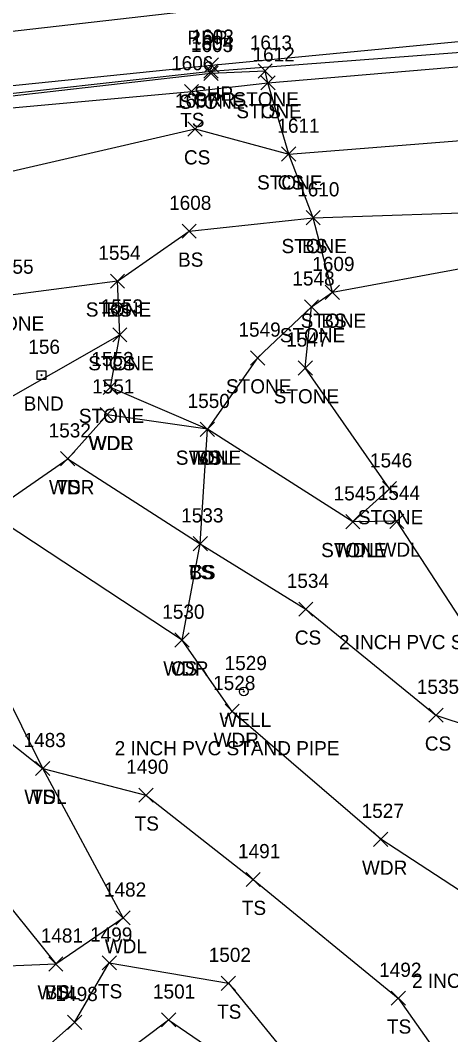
# Model space of a CAD drawing. Extents: x 49137 to 50946, y 9590 to 10709.
# Drawn here: x 50177.5 to 50238.1, y 9912 to 10054.9 of the extents above; entities that cross this region are included whole.
import ezdxf

# ---------------------------------------------------------------- set-up
doc = ezdxf.new("R2010")
doc.units = 0
for name, color, linetype in [('L_A', 7, 'Continuous'), ('L_I', 7, 'Continuous'), ('L_TIC', 7, 'Continuous'), ('LASF', 7, 'Continuous'), ('LAWA', 7, 'Continuous'), ('LAWE', 7, 'Continuous'), ('LELB', 7, 'Continuous'), ('M_A', 7, 'Continuous'), ('M_I', 7, 'Continuous'), ('MHBP', 7, 'Continuous'), ('P_A', 7, 'Continuous'), ('P_I', 7, 'Continuous'), ('P_TIC', 7, 'Continuous'), ('PET', 7, 'Continuous'), ('PSP', 7, 'Continuous'), ('R_A', 7, 'Continuous'), ('R_I', 7, 'Continuous'), ('R_TIC', 7, 'Continuous'), ('RGR', 7, 'Continuous'), ('U_A', 7, 'Continuous'), ('U_C', 7, 'Continuous'), ('U_I', 7, 'Continuous'), ('UWW', 7, 'Continuous')]:
    doc.layers.add(name, color=color, linetype=linetype)

msp = doc.modelspace()

# ---------------------------------------------------------------- linework, layer by layer
at = {"layer": 'L_TIC'}
for points in [[(50203.29, 10046.45), (50205.29, 10048.45)], [(50205.29, 10046.45), (50203.29, 10048.45)], [(50210.93, 10046.79), (50212.93, 10048.79)], [(50212.93, 10046.79), (50210.93, 10048.79)], [(50210.93, 10046.79), (50212.93, 10048.79)], [(50212.93, 10046.79), (50210.93, 10048.79)], [(50211.32, 10045.12), (50213.32, 10047.12)], [(50213.32, 10045.12), (50211.32, 10047.12)], [(50211.32, 10045.12), (50213.32, 10047.12)], [(50213.32, 10045.12), (50211.32, 10047.12)], [(50200.55, 10043.88), (50202.55, 10045.88)], [(50202.55, 10043.88), (50200.55, 10045.88)], [(50201.05, 10038.61), (50203.05, 10040.61)], [(50203.05, 10038.61), (50201.05, 10040.61)], [(50214.24, 10035.08), (50216.24, 10037.08)], [(50216.24, 10035.08), (50214.24, 10037.08)], [(50214.24, 10035.08), (50216.24, 10037.08)], [(50216.24, 10035.08), (50214.24, 10037.08)], [(50217.69, 10026.11), (50219.69, 10028.11)], [(50219.69, 10026.11), (50217.69, 10028.11)], [(50217.69, 10026.11), (50219.69, 10028.11)], [(50219.69, 10026.11), (50217.69, 10028.11)], [(50217.69, 10026.11), (50219.69, 10028.11)], [(50219.69, 10026.11), (50217.69, 10028.11)], [(50200.22, 10024.2), (50202.22, 10026.2)], [(50202.22, 10024.2), (50200.22, 10026.2)], [(50190.13, 10017.17), (50192.13, 10019.17)], [(50192.13, 10017.17), (50190.13, 10019.17)], [(50190.13, 10017.17), (50192.13, 10019.17)], [(50192.13, 10017.17), (50190.13, 10019.17)], [(50220.39, 10015.59), (50222.39, 10017.59)], [(50222.39, 10015.59), (50220.39, 10017.59)], [(50220.39, 10015.59), (50222.39, 10017.59)], [(50222.39, 10015.59), (50220.39, 10017.59)], [(50217.45, 10013.55), (50219.45, 10015.55)], [(50219.45, 10013.55), (50217.45, 10015.55)], [(50217.45, 10013.55), (50219.45, 10015.55)], [(50219.45, 10013.55), (50217.45, 10015.55)], [(50190.47, 10009.6), (50192.47, 10011.6)], [(50192.47, 10009.6), (50190.47, 10011.6)], [(50190.47, 10009.6), (50192.47, 10011.6)], [(50192.47, 10009.6), (50190.47, 10011.6)], [(50209.87, 10006.34), (50211.87, 10008.34)], [(50211.87, 10006.34), (50209.87, 10008.34)], [(50216.58, 10004.94), (50218.58, 10006.94)], [(50218.58, 10004.94), (50216.58, 10006.94)], [(50189.14, 10002.19), (50191.14, 10004.19)], [(50191.14, 10002.19), (50189.14, 10004.19)], [(50188.69, 9998.35), (50190.69, 10000.35)], [(50190.69, 9998.35), (50188.69, 10000.35)], [(50188.69, 9998.35), (50190.69, 10000.35)], [(50190.69, 9998.35), (50188.69, 10000.35)], [(50202.79, 9996.29), (50204.79, 9998.29)], [(50204.79, 9996.29), (50202.79, 9998.29)], [(50202.79, 9996.29), (50204.79, 9998.29)], [(50204.79, 9996.29), (50202.79, 9998.29)], [(50202.79, 9996.29), (50204.79, 9998.29)], [(50204.79, 9996.29), (50202.79, 9998.29)], [(50183.13, 9992.14), (50185.13, 9994.14)], [(50185.13, 9992.14), (50183.13, 9994.14)], [(50183.13, 9992.14), (50185.13, 9994.14)], [(50185.13, 9992.14), (50183.13, 9994.14)], [(50228.44, 9987.91), (50230.44, 9989.91)], [(50230.44, 9987.91), (50228.44, 9989.91)], [(50223.27, 9983.27), (50225.27, 9985.27)], [(50225.27, 9983.27), (50223.27, 9985.27)], [(50223.27, 9983.27), (50225.27, 9985.27)], [(50225.27, 9983.27), (50223.27, 9985.27)], [(50229.47, 9983.33), (50231.47, 9985.33)], [(50231.47, 9983.33), (50229.47, 9985.33)], [(50201.79, 9980.16), (50203.79, 9982.16)], [(50203.79, 9980.16), (50201.79, 9982.16)], [(50201.79, 9980.16), (50203.79, 9982.16)], [(50203.79, 9980.16), (50201.79, 9982.16)], [(50201.79, 9980.16), (50203.79, 9982.16)], [(50203.79, 9980.16), (50201.79, 9982.16)], [(50216.66, 9970.94), (50218.66, 9972.94)], [(50218.66, 9970.94), (50216.66, 9972.94)], [(50199.22, 9966.59), (50201.22, 9968.59)], [(50201.22, 9966.59), (50199.22, 9968.59)], [(50199.22, 9966.59), (50201.22, 9968.59)], [(50201.22, 9966.59), (50199.22, 9968.59)], [(50206.29, 9956.54), (50208.29, 9958.54)], [(50208.29, 9956.54), (50206.29, 9958.54)], [(50234.97, 9956.01), (50236.97, 9958.01)], [(50236.97, 9956.01), (50234.97, 9958.01)], [(50179.6, 9948.5), (50181.6, 9950.5)], [(50181.6, 9948.5), (50179.6, 9950.5)], [(50179.6, 9948.5), (50181.6, 9950.5)], [(50181.6, 9948.5), (50179.6, 9950.5)], [(50194.14, 9944.74), (50196.14, 9946.74)], [(50196.14, 9944.74), (50194.14, 9946.74)], [(50227.2, 9938.52), (50229.2, 9940.52)], [(50229.2, 9938.52), (50227.2, 9940.52)], [(50209.23, 9932.85), (50211.23, 9934.85)], [(50211.23, 9932.85), (50209.23, 9934.85)], [(50190.92, 9927.44), (50192.92, 9929.44)], [(50192.92, 9927.44), (50190.92, 9929.44)], [(50181.45, 9920.95), (50183.45, 9922.95)], [(50183.45, 9920.95), (50181.45, 9922.95)], [(50181.45, 9920.95), (50183.45, 9922.95)], [(50183.45, 9920.95), (50181.45, 9922.95)], [(50188.98, 9921.1), (50190.98, 9923.1)], [(50190.98, 9921.1), (50188.98, 9923.1)], [(50205.75, 9918.23), (50207.75, 9920.23)], [(50207.75, 9918.23), (50205.75, 9920.23)], [(50229.67, 9916.13), (50231.67, 9918.13)], [(50231.67, 9916.13), (50229.67, 9918.13)], [(50197.34, 9913.07), (50199.34, 9915.07)], [(50199.34, 9913.07), (50197.34, 9915.07)], [(50184.1, 9912.72), (50186.1, 9914.72)], [(50186.1, 9912.72), (50184.1, 9914.72)]]:
    msp.add_lwpolyline(points, dxfattribs=at)
at = {"layer": 'LASF'}
for points in [[(50075.14, 9979.09), (50069.31, 9989.49), (50063.31, 10003.63), (50083.24, 10011.13), (50103.65, 10019.31), (50102.01, 10030.98), (50101.92, 10032.21), (50138.71, 10039.2), (50167.18, 10043.25), (50204.29, 10047.45), (50211.93, 10047.79)], [(50224.27, 9984.27), (50229.44, 9988.91), (50217.58, 10005.94), (50218.45, 10014.55), (50221.39, 10016.59), (50218.69, 10027.11), (50215.24, 10036.08), (50212.32, 10046.12), (50211.93, 10047.79)], [(50218.45, 10014.55), (50210.87, 10007.34), (50203.79, 9997.29), (50190.14, 10003.19), (50191.47, 10010.6), (50191.13, 10018.17), (50176.06, 10016.21), (50169.79, 10016.59), (50164.12, 10007.94)]]:
    msp.add_lwpolyline(points, dxfattribs=at)
at = {"layer": 'LAWA'}
for points in [[(50265.38, 9914.66), (50247, 9927.27), (50228.2, 9939.52), (50207.29, 9957.54), (50200.22, 9967.59), (50173.05, 9985.49), (50184.13, 9993.14), (50189.69, 9999.35)], [(50319.22, 9934.09), (50297.9, 9949.71), (50276.2, 9961.58), (50260.59, 9967.74), (50240.67, 9968.69), (50230.47, 9984.33), (50224.27, 9984.27), (50203.79, 9997.29), (50189.69, 9999.35)], [(50117.09, 9812.03), (50125.19, 9838.2), (50131.44, 9869.96), (50136.76, 9887.6), (50137.75, 9904.59), (50153.56, 9910.03), (50161.77, 9913.05), (50163.42, 9912.91), (50169.87, 9921.06), (50171.08, 9921.49), (50182.45, 9921.95), (50191.92, 9928.44), (50180.6, 9949.5), (50171.66, 9967.48), (50163.03, 9983.02), (50150.28, 9995.84), (50140.4, 9991.18), (50131.52, 9978.47)]]:
    msp.add_lwpolyline(points, dxfattribs=at)
at = {"layer": 'LAWE'}
msp.add_lwpolyline([(50128.8, 9830.05), (50134.29, 9847.3), (50142.11, 9880.9), (50145.47, 9899.84), (50152.79, 9899.24), (50158.84, 9904.9), (50168.73, 9907.32), (50170.14, 9900.19), (50173.37, 9900.16), (50184.59, 9903.76), (50198.34, 9914.07), (50214.56, 9902.92), (50226.92, 9887.06)], dxfattribs=at)
at = {"layer": 'LELB'}
for points in [[(50167.44, 10041.81), (50201.55, 10044.88), (50212.32, 10046.12), (50246.1, 10048.99), (50272.8, 10048.46), (50313.94, 10048.62), (50350.81, 10048.34), (50387.74, 10046.03), (50413.04, 10045.35), (50435.45, 10042.61), (50477, 10035.72), (50497.96, 10034.79)], [(50107.47, 10020.38), (50144.2, 10028.78), (50165.65, 10031.22), (50202.05, 10039.61), (50215.24, 10036.08), (50246.55, 10038.53), (50272.19, 10036.43), (50315.22, 10038.43), (50350.77, 10037.74), (50388.31, 10038.81), (50412.12, 10038.05), (50434.22, 10033.95), (50476.27, 10030.6), (50502.33, 10026.06), (50519.95, 10026.12), (50528.33, 10023.44), (50558.5, 10017.09), (50596.1, 10007.75), (50623.13, 10001.96)], [(50218.69, 10027.11), (50246.54, 10028.02), (50268.1, 10028.33), (50270.89, 10027.37)], [(50191.13, 10018.17), (50201.22, 10025.2), (50218.69, 10027.11)], [(50221.39, 10016.59), (50240.69, 10020.2), (50266.27, 10022.79), (50262.95, 10002.37)], [(50150.28, 9995.84), (50172.85, 9999.99), (50191.47, 10010.6)], [(50202.79, 9981.16), (50203.79, 9997.29)], [(50184.13, 9993.14), (50202.79, 9981.16)], [(50200.22, 9967.59), (50202.79, 9981.16), (50217.66, 9971.94), (50235.97, 9957.01), (50255.74, 9950.49), (50271.41, 9942.16)], [(50154.36, 9970.3), (50163.69, 9962.94), (50180.6, 9949.5), (50195.14, 9945.74), (50210.23, 9933.85), (50230.67, 9917.13), (50242.1, 9900.88)], [(50151.54, 9966.17), (50159.46, 9958.1), (50157.64, 9954.79), (50157.4, 9946.13), (50160.15, 9939.02), (50167.35, 9930.31), (50171.08, 9921.49), (50172.89, 9902.89), (50185.1, 9913.72), (50189.98, 9922.1), (50206.75, 9919.23), (50216.84, 9906.82), (50233.45, 9889.39)], [(50157.64, 9954.79), (50163.27, 9946.54), (50167.1, 9940.71), (50172.95, 9933.72), (50182.45, 9921.95)]]:
    msp.add_lwpolyline(points, dxfattribs=at)
at = {"layer": 'MHBP'}
msp.add_lwpolyline([(50179.81, 10005.55), (50181.06, 10005.55), (50181.06, 10004.3), (50179.81, 10004.3)], close=True, dxfattribs=at)
msp.add_circle((50180.43, 10004.92), 0.0833, dxfattribs=at)
at = {"layer": 'P_TIC'}
for points in [[(50203.38, 10047.62), (50205.38, 10049.62)], [(50205.38, 10047.62), (50203.38, 10049.62)]]:
    msp.add_lwpolyline(points, dxfattribs=at)
at = {"layer": 'PET'}
msp.add_lwpolyline([(49743.42, 9944.81), (49788.35, 9958.02), (49837.04, 9971.51), (49882.75, 9984.49), (49918.64, 9994.5), (49951.14, 10003.99), (49990.91, 10015.05), (50038.8, 10027.76), (50078.38, 10036.75), (50102.79, 10041.88), (50136.94, 10048.02), (50166.81, 10052.31), (50203.48, 10056.47), (50244.74, 10059.59), (50274.3, 10060.67), (50312.69, 10061.26), (50351.88, 10059.79), (50388.42, 10057.55), (50415.03, 10055.45), (50437.05, 10053.05), (50478.42, 10048.42), (50499.95, 10044.65)], dxfattribs=at)
at = {"layer": 'PSP'}
msp.add_lwpolyline([(49745.77, 9936.94), (49791.02, 9949.79), (49838.6, 9962.98), (49884.65, 9976.31), (49920.32, 9986.67), (49952.97, 9996.21), (49993.49, 10007.72), (50041.55, 10020.44), (50079.02, 10029.05), (50103.84, 10034.11), (50138.34, 10040.53), (50167.13, 10044.8), (50204.38, 10048.62), (50245.47, 10052.53), (50273.99, 10052.71), (50313.27, 10053.81), (50350.86, 10052.67), (50388.17, 10050.83), (50414.17, 10048.89), (50435.24, 10046.38), (50477.89, 10041.39), (50498.49, 10037.53)], dxfattribs=at)
at = {"layer": 'R_TIC'}
for points in [[(50203.31, 10046.75), (50205.31, 10048.75)], [(50205.31, 10046.75), (50203.31, 10048.75)]]:
    msp.add_lwpolyline(points, dxfattribs=at)
at = {"layer": 'RGR'}
msp.add_lwpolyline([(49745.96, 9935.74), (49791.34, 9948.66), (49838.49, 9962.28), (49885.39, 9975.73), (49920.7, 9985.37), (49953.18, 9995.29), (49993.74, 10006.79), (50040.75, 10019.43), (50079.3, 10027.88), (50102.09, 10032.68), (50138.52, 10039.64), (50167.15, 10043.61), (50204.31, 10047.75), (50245.69, 10050.91), (50273.98, 10052), (50313.38, 10052.67), (50351, 10051.76), (50388.09, 10049.85), (50414.02, 10047.85), (50436.27, 10045.35), (50477.66, 10040.11), (50498.48, 10036.57)], dxfattribs=at)
at = {"layer": 'UWW'}
for radius in [0.625, 0.0833]:
    msp.add_circle((50208.92, 9960.35), radius, dxfattribs=at)

# ---------------------------------------------------------------- texts
at = {"layer": 'L_A'}
for s, p in [('STONE', (50199.83, 10042.45)), ('STONE', (50207.47, 10042.79)), ('STONE', (50207.47, 10042.79)), ('STONE', (50207.87, 10041.12)), ('TS', (50210.73, 10041.12)), ('TS', (50199.96, 10039.88)), ('CS', (50200.49, 10034.61)), ('STONE', (50210.79, 10031.08)), ('CS', (50213.68, 10031.08)), ('STONE', (50214.23, 10022.11)), ('BS', (50217.13, 10022.11)), ('BS', (50217.13, 10022.11)), ('BS', (50199.66, 10020.2)), ('STONE', (50186.67, 10013.17)), ('BS', (50189.57, 10013.17)), ('STONE', (50216.93, 10011.59)), ('BS', (50219.83, 10011.59)), ('STONE', (50171.61, 10011.21)), ('STONE', (50213.99, 10009.55)), ('STONE', (50213.99, 10009.55)), ('STONE', (50187.02, 10005.6)), ('CS', (50189.91, 10005.6)), ('STONE', (50206.41, 10002.34)), ('STONE', (50213.13, 10000.94)), ('STONE', (50185.69, 9998.19)), ('WDR', (50187.05, 9994.35)), ('WDL', (50187.11, 9994.35)), ('STONE', (50199.34, 9992.29)), ('WDL', (50201.21, 9992.29)), ('BS', (50202.23, 9992.29)), ('WDR', (50181.49, 9988.14)), ('TS', (50182.54, 9988.14)), ('STONE', (50224.98, 9983.91)), ('STONE', (50219.81, 9979.27)), ('WDL', (50221.68, 9979.27)), ('WDL', (50227.89, 9979.33)), ('TS', (50201.2, 9976.16)), ('CS', (50201.23, 9976.16)), ('BS', (50201.23, 9976.16)), ('CS', (50216.1, 9966.94)), ('WDR', (50197.58, 9962.59)), ('CS', (50198.66, 9962.59)), ('WDR', (50204.66, 9952.54)), ('CS', (50234.41, 9952.01)), ('WDL', (50178.02, 9944.5)), ('TS', (50179.01, 9944.5)), ('TS', (50193.55, 9940.74)), ('WDR', (50225.56, 9934.52)), ('TS', (50208.64, 9928.85)), ('WDL', (50189.34, 9923.44)), ('TS', (50188.39, 9917.1)), ('WDL', (50179.87, 9916.95)), ('BS', (50180.89, 9916.95)), ('TS', (50205.16, 9914.23)), ('TS', (50229.08, 9912.13))]:
    msp.add_text(s, height=2, dxfattribs=at).set_placement(p)
at = {"layer": 'L_I'}
for s, p in [('1605', (50201.47, 10050.45)), ('1613', (50209.76, 10050.79)), ('1613', (50209.76, 10050.79)), ('1612', (50210.15, 10049.12)), ('1612', (50210.15, 10049.12)), ('1606', (50198.68, 10047.88)), ('1607', (50199.23, 10042.61)), ('1611', (50213.64, 10039.08)), ('1611', (50213.64, 10039.08)), ('1610', (50216.43, 10030.11)), ('1610', (50216.43, 10030.11)), ('1610', (50216.43, 10030.11)), ('1608', (50198.4, 10028.2)), ('1554', (50188.44, 10021.17)), ('1554', (50188.44, 10021.17)), ('1555', (50173.37, 10019.21)), ('1609', (50218.56, 10019.59)), ('1609', (50218.56, 10019.59)), ('1548', (50215.76, 10017.55)), ('1548', (50215.76, 10017.55)), ('1553', (50188.78, 10013.6)), ('1553', (50188.78, 10013.6)), ('1549', (50208.17, 10010.34)), ('1547', (50214.89, 10008.94)), ('1552', (50187.45, 10006.19)), ('1551', (50187.56, 10002.35)), ('1551', (50187.56, 10002.35)), ('1550', (50201.01, 10000.29)), ('1550', (50201.01, 10000.29)), ('1550', (50201.01, 10000.29)), ('1532', (50181.44, 9996.14)), ('1532', (50181.44, 9996.14)), ('1546', (50226.69, 9991.91)), ('1545', (50221.57, 9987.27)), ('1545', (50221.57, 9987.27)), ('1544', (50227.78, 9987.33)), ('1533', (50200.1, 9984.16)), ('1533', (50200.1, 9984.16)), ('1533', (50200.1, 9984.16)), ('1534', (50214.97, 9974.94)), ('1530', (50197.44, 9970.59)), ('1530', (50197.44, 9970.59)), ('1528', (50204.6, 9960.54)), ('1535', (50233.28, 9960.01)), ('1483', (50177.91, 9952.5)), ('1483', (50177.91, 9952.5)), ('1490', (50192.36, 9948.74)), ('1527', (50225.51, 9942.52)), ('1491', (50208.11, 9936.85)), ('1482', (50189.23, 9931.44)), ('1481', (50180.33, 9924.95)), ('1481', (50180.33, 9924.95)), ('1499', (50187.28, 9925.1)), ('1502', (50203.98, 9922.23)), ('1492', (50227.98, 9920.13)), ('1501', (50196.13, 9917.07)), ('1498', (50182.41, 9916.72))]:
    msp.add_text(s, height=2, dxfattribs=at).set_placement(p)
at = {"layer": 'M_A'}
msp.add_text('BND', height=2, dxfattribs=at).set_placement((50177.92, 9999.92))
at = {"layer": 'M_I'}
msp.add_text('156', height=2, dxfattribs=at).set_placement((50178.58, 10007.92))
at = {"layer": 'P_A'}
for s, p in [('RDP', (50200.97, 10051.47)), ('SHP', (50201.91, 10043.62))]:
    msp.add_text(s, height=2, dxfattribs=at).set_placement(p)
at = {"layer": 'P_I'}
msp.add_text('1603', height=2, dxfattribs=at).set_placement((50201.56, 10051.62))
at = {"layer": 'R_A'}
msp.add_text('GRR', height=2, dxfattribs=at).set_placement((50201.8, 10042.75))
at = {"layer": 'R_I'}
msp.add_text('1604', height=2, dxfattribs=at).set_placement((50201.49, 10050.75))
at = {"layer": 'U_A'}
msp.add_text('WELL', height=2, dxfattribs=at).set_placement((50205.49, 9955.35))
at = {"layer": 'U_C'}
for s, p in [('2 INCH PVC STAND PIPE INCASAE 4', (50222.31, 9966.3)), ('2 INCH PVC STAND PIPE', (50190.74, 9951.35)), ('2 INCH PVC STAND PIPE', (50232.62, 9918.58))]:
    msp.add_text(s, height=2, dxfattribs=at).set_placement(p)
at = {"layer": 'U_I'}
msp.add_text('1529', height=2, dxfattribs=at).set_placement((50206.22, 9963.35))

doc.saveas('drawing.dxf')
